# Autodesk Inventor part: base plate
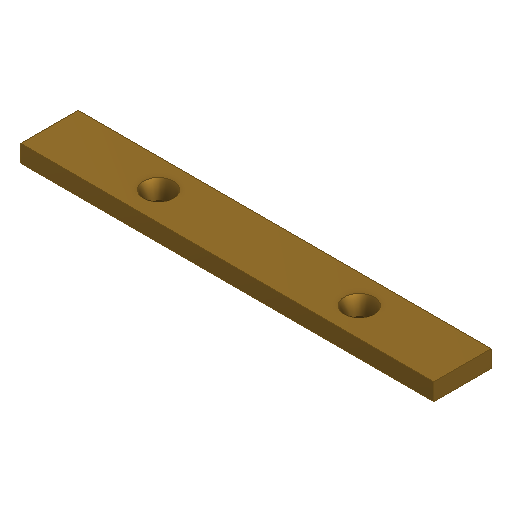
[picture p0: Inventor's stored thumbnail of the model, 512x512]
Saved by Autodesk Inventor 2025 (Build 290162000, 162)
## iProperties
Created: 2016-03
Part Number: base plate
Material: Generic
Document SubType Name: Modeling
Designer: Sandeep
Density: 1 g/cm^3
Appearance: Default
Mass: 16.6527 g
Surface Area: 78.2446 cm^2
Volume: 16.6527 cm^3
Author: Sandeep
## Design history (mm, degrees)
sketch "Sketch1"
  geometry: L1 (0, 0)-(144, 0); L2 (144, 0)-(144, 20); L3 (144, 20)-(0, 20); L4 (0, 20)-(0, 0)
  constraints: 8 end point, 2 parallel, 1 horizontal, 1 perpendicular
  dimensions: "d0" = 144 distance of L1.start L1.end; "d1" = 20 distance of L1.end L2.end
extrude "Extrusion1" new body sketch "Sketch1" distance "d2" = 6; taper "d3" = 0 deg
sketch "Sketch2"
  geometry: L1 (0, 20)-(0, 0) reference; L2 (0, 10)-(181.292, 10); 2 further points
  constraints: 2 end point, 2 point on line, 1 horizontal, 1 midpoint
  dimensions: "d4" = 70 distance of point (108, 10) point (38, 10); "d5" = 38 distance from line of L1 point (38, 10)
hole "Hole1" sketch "Sketch2" at (38, 10), (108, 10) diameter "d6" = 6; stored, may be unused: countersink angle "d10" = 45 deg, drill point angle "d12" = 118 deg; dims "d7" = 6, "d8" = 10.5, "d9" = 2, "d11" = 8
body "Solid1"
